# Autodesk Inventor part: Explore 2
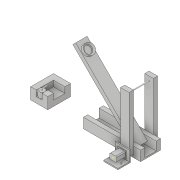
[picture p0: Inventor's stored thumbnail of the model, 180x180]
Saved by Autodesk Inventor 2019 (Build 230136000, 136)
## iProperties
Created: 2020-02
Part Number: Explore 2
Material: Generic
Document SubType Name: Modeling
Designer: Naveen G
Density: 1 g/cm^3
Appearance: Default
Author: Naveen G
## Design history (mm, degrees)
sketch "Sketch1"
  geometry: 1 further point
sketch "Sketch2"
  geometry: L1 (0, 0)-(40, 0); L2 (40, 0)-(40, 15); L3 (40, 15)-(-160, 15); L4 (-160, 15)-(-160, -15); L5 (-160, -15)-(40, -15); L6 (40, -15)-(40, 15)
  constraints: 12 end point, 3 perpendicular, 1 horizontal, 1 point on line
  dimensions: "d0" = 40 distance of L1.start L1.end; "d1" = 15 distance of L1.end L2.end; "d2" = 200 distance of L2.end L3.end; "d3" = 30 distance of L3.end L4.end; "d4" = 200 distance of L4.end L5.end
extrude "Extrusion1" new body sketch "Sketch2" distance "d5" = 15; taper "d6" = 0 deg
sketch "Sketch3"
  geometry: L1 (0, 0)-(0, -10); L2 (0, -10)-(10, 0); L3 (10, 0)-(-202.132, 212.132); L4 (0, -10)-(-212.132, 202.132); L5 (0, -10)-(300, -10); L6 (-212.132, 202.132)-(-202.132, 212.132)
  constraints: 12 end point, 2 perpendicular, 1 equal length, 1 horizontal, 1 vertical
  dimensions: "d7" = 10 distance of L1.start L1.end; "d8" = 45 deg angle of L2 L1; "d9" = 300 distance of L2.end L3.end; "d10" = 90 deg angle of L3 L2 (derived); "d11" = 300 distance of L1.end L4.end; "d12" = 135 deg angle of L5 L4
sketch "Sketch4"
  geometry: 1 further point
extrude "Extrusion2" join sketch "Sketch3" distance "d13" = 40; taper "d14" = 0 deg
sketch "Sketch5"
  geometry: L1 (0, 0)-(40, 0); L2 (40, -15)-(40, 15) reference; L3 (40, 15)-(-160, 15); L4 (40, 15)-(-5, 15) reference; L5 (-160, 15)-(-160, -15) reference; L6 (-160, 15)-(-160, -15); L7 (-160, -15)-(40, -15) reference; L8 (-160, -15)-(40, -15); L9 (40, -15)-(40, 15)
  constraints: 10 end point, 2 collinear, 2 perpendicular, 1 midpoint
  dimensions: "d15" = 200 distance of L2.end L3.end
extrude "Extrusion3" join sketch "Sketch5" distance "d16" = 15; taper "d17" = 0 deg
sketch "Sketch6"
  geometry: L1 (0, 0)-(0, -15); L2 (-160, -15)-(40, -15) reference; L3 (0, -15)-(15, -15); L4 (15, -15)-(15, 185); L5 (15, 185)-(15, -2.705); L6 (15, 185)-(-15, 185); L7 (-15, 185)-(-15, -15); L8 (-15, -15)-(0, -15)
  constraints: 14 end point, 4 perpendicular, 3 point on line, 1 vertical
  dimensions: "d18" = 15 distance of L1.end L3.end; "d19" = 200 distance of L3.end L4.end; "d20" = 30 distance of L4.end L6.end; "d21" = 200 distance of L6.end L7.end
extrude "Extrusion4" join sketch "Sketch6" distance "d22" = 15; taper "d23" = 0 deg
sketch "Sketch7"
  geometry: L1 (0, 0)-(0, 15) reference; L2 (0, 0)-(0, 70); L3 (0, 70)-(200, 70); L4 (200, 70)-(200, 0); L5 (200, 0)-(0, 0) reference; L6 (200, 0)-(0, 0); 1 further point
  constraints: 8 end point, 2 collinear, 2 perpendicular
  dimensions: "d24" = 70 distance of L1.start L2.end; "d25" = 200 distance of L2.end L3.end; "d26" = 200 distance of L4.end L1.start (derived)
extrude "Extrusion5" join sketch "Sketch7" distance "d27" = 5; taper "d28" = 0 deg
fillet "Fillet1" dims "d29" = 5
fillet "Fillet2" dims "d30" = 5
sketch "Sketch8"
  geometry: 1 further point
sketch "Sketch9"
  geometry: L1 (-15, -10)-(-15, 185) reference; L2 (-15, 185)-(15, 185) reference; L3 (-15, 185)-(15, 185); L4 (15, 185)-(15, -15); L5 (-15, 185)-(-15, -15); L6 (10, -15)-(-10, -15) reference; L7 (-15, -15)-(15, -15); 1 further point
  constraints: 8 end point, 1 collinear, 1 perpendicular, 1 point on line
  dimensions: "d31" = 30 distance of L1.end L2.end (derived); "d32" = 200 distance of L2.end L4.end; "d33" = 200 distance of L1.end L5.end; "d34" = 30 distance of L5.end L4.end (derived)
extrude "Extrusion6" join sketch "Sketch9" distance "d35" = 15; taper "d36" = 0 deg
fillet "Fillet3" dims "d37" = 5
sketch "Sketch10"
  geometry: L1 (-15, 185)-(15, 185) reference; L2 (0, 185)-(0, 170); C1 r 2 at (0, 170); 1 further point
  constraints: 2 end point, 1 centre point, 1 coincident, 1 midpoint, 1 vertical
  dimensions: "d38" = 15 distance of L2.start L2.end; "d39" = 4 diameter of C1
extrude "Extrusion7" join sketch "Sketch10" distance "d40" = 70; taper "d41" = 0 deg
sketch "Sketch11"
  geometry: L1 (0, 0)-(0, 40) reference; L2 (0, 0)-(0, 20); L3 (0, 20)-(-30, 20); C1 r 17.5 at (-30, 20); C2 r 12.5 at (-30, 20); 1 further point
  constraints: 4 end point, 2 centre point, 2 coincident, 1 midpoint, 1 perpendicular
  dimensions: "d42" = 20 distance of L1.start L2.end (derived); "d43" = 30 distance of L2.end L3.end; "d44" = 35 diameter of C1; "d45" = 25 diameter of C2
extrude "Extrusion8" join sketch "Sketch11" distance "d46" = 10; taper "d47" = 0 deg
chamfer "Chamfer1" distance "d48" = 5; stored, may be unused: second distance "d49" = 1.25, angle "d50" = 45 deg
sketch "Sketch12"
  geometry: C1 r 3.5 at (0, 0); 1 further point
  constraints: 1 centre point, 1 coincident
  dimensions: "d51" = 7 diameter of C1
extrude "Extrusion9" join sketch "Sketch12" distance "d52" = 5; taper "d53" = 0 deg
sketch "Sketch13"
  geometry: C1 r 3.5 at (0, 0); 1 further point
  constraints: 1 centre point, 1 coincident
extrude "Extrusion10" join sketch "Sketch13" distance "d54" = 5; taper "d55" = 0 deg
fillet "Fillet4" dims "d56" = 3
sketch "Sketch14"
  geometry: L1 (0, 0)-(25, 0); L2 (25, 0)-(25, 20); L3 (25, 20)-(-25, 20); L4 (-25, 20)-(-25, -20); L5 (-160, -20)-(40, -20) reference; L6 (25, -20)-(25, 0); C1 r 0.5 at (0, 0) reference; 1 further point
  constraints: 10 end point, 4 perpendicular, 3 point on line, 1 horizontal
  dimensions: "d57" = 25 distance of L1.start L1.end; "d58" = 20 distance of L1.end L2.end; "d59" = 50 distance of L2.end L3.end
extrude "Extrusion11" join sketch "Sketch14" distance "d60" = 4; taper "d61" = 0 deg
sketch "Sketch15"
  geometry: L1 (-25, 20)-(-25, -20) reference; L2 (-25, -20)-(25, -20); L3 (25, -20)-(25, -16); L4 (25, -16)-(-25, -16); L5 (-25, -16)-(-25, -20); 1 further point
  constraints: 8 end point, 2 parallel, 1 horizontal, 1 perpendicular
  dimensions: "d62" = 50 distance of L4.end L3.end; "d63" = 4 distance of L3.end L2.end
extrude "Extrusion12" join sketch "Sketch15" distance "d64" = 40; taper "d65" = 0 deg
sketch "Sketch16"
  geometry: L1 (0, -40)-(50, -40) reference; L2 (0, -40)-(0, -20); L3 (0, 4)-(0, -40) reference; L4 (0, -20)-(50, -20); L5 (50, -20)-(42, -20); L6 (42, -20)-(0, -20); L7 (0, -20)-(7.932, -20); L8 (0, -20)-(8, -20); C1 r 2 at (42, -20); C2 r 2 at (8, -20); 1 further point
  constraints: 12 end point, 4 point on line, 2 centre point, 2 coincident, 2 perpendicular
  dimensions: "d66" = 20 distance of L1.start L2.end; "d67" = 50 distance of L2.end L4.end; "d68" = 8 distance of L4.end L5.end; "d69" = 8 distance of L2.end L8.end; "d70" = 4 diameter of C1; "d71" = 4 diameter of C2
extrude "Extrusion13" join sketch "Sketch16" distance "d72" = 3; taper "d73" = 0 deg
sketch "Sketch17"
  geometry: L1 (0, 0)-(0, -12.5); L2 (0, -12.5)-(15, -12.5); L3 (15, -12.5)-(15, 12.5); L4 (15, 185)-(15, -10) reference; L5 (15, 12.5)-(-15, 12.5); L6 (-15, 12.5)-(-15, -12.5); L7 (-15, -12.5)-(0, -12.5); C1 r 0.5 at (0, 0) reference; 1 further point
  constraints: 12 end point, 2 point on line, 1 horizontal, 1 perpendicular, 1 vertical
  dimensions: "d74" = 12.5 distance of L1.start L1.end; "d75" = 15 distance of L1.end L2.end; "d76" = 25 distance of L2.end L3.end; "d77" = 30 distance of L3.end L5.end; "d78" = 25 distance of L5.end L6.end
sketch "Sketch18"
  geometry: L1 (15, 185)-(15, -10) reference; L2 (15, 12.495)-(15, 6.245); L3 (15, 0)-(15, -6.25); L4 (15, -6.25)-(15, -12.5); L5 (15, -12.5)-(15, 12.495); 1 further point
  constraints: 8 end point, 5 point on line, 1 collinear
  dimensions: "d79" = 6.25 distance of L2.start L2.end; "d80" = 6.25 distance of L3.start L3.end; "d81" = 6.25 distance of L3.end L4.end
sketch "Sketch19"
  geometry: 1 further point
sketch "Sketch20"
  geometry: L1 (-15, -10)-(-15, 185) reference; L2 (-15, 11.25)-(-15, 9.383); L3 (-15, 5)-(-15, -7.5); L4 (-25, 15)-(0, -10) reference; C1 r 3.25 at (16.5, 6.253); C2 r 3.25 at (16.5, -6.247); C3 r 3.25 at (-16.5, -6.247); A1 r 3.25 centre (-16.5, 6.5) between (-15, 9.383) and (-14.202, 4.202); 1 further point
  constraints: 5 point on line, 4 centre point, 4 end point, 2 point on circle
  dimensions: "d82" = 6.25 distance of L2.start L3.start; "d83" = 12.5 distance of L3.start L3.end; "d84" = 6.5 diameter of C1; "d85" = 6.5 diameter of C2; "d86" = 6.5 diameter of A1; "d87" = 6.5 diameter of C3
extrude "Extrusion14" join sketch "Sketch17" distance "d88" = 2; taper "d89" = 0 deg
sketch "Sketch21"
  geometry: L1 (0, 0)-(12, 0); L2 (12, 0)-(12, 9.5); L3 (12, 9.5)-(-12, 9.5); L4 (-12, 9.5)-(-12, -9.5); L5 (-12, -9.5)-(12, -9.5); L6 (12, 0)-(12, -9.5); C1 r 3.5 at (0, 0) reference; 1 further point
  constraints: 12 end point, 2 perpendicular, 2 vertical, 1 horizontal, 1 point on line
  dimensions: "d90" = 12 distance of L1.start L1.end; "d91" = 9.5 distance of L1.end L2.end; "d92" = 24 distance of L2.end L3.end; "d93" = 19 distance of L3.end L4.end; "d94" = 24 distance of L4.end L5.end; "d95" = 9.5 distance of L1.end L5.end (derived)
extrude "Extrusion15" join sketch "Sketch21" distance "d96" = 30; taper "d97" = 0 deg
sketch "Sketch22"
  geometry: C1 r 0.5 at (0, 0) reference; C2 r 3.5 at (0, 0); 1 further point
  constraints: 1 centre point, 1 coincident
  dimensions: "d98" = 7 diameter of C2
sketch "Sketch23"
  geometry: 1 further point
sketch "Sketch24"
  geometry: C1 r 3.5 at (0, 0); 1 further point
  constraints: 1 centre point, 1 coincident
  dimensions: "d99" = 7 diameter of C1
extrude "Extrusion16" join sketch "Sketch24" distance "d100" = 30; taper "d101" = 0 deg
fillet "Fillet5" dims "d102" = 3
sketch "Sketch25"
  geometry: L1 (0, 70)-(0, 0) reference; L2 (0, 0)-(-120, 0); L3 (-120, 0)-(-120, 10); L4 (-120, 10)-(-120, 15); L5 (-52.132, 15)-(135, 15) reference; L6 (-120, 15)-(-120, 75); L7 (-120, 75)-(-180, 75); L8 (-180, 75)-(-180, -5); L9 (-180, -5)-(-120, -5); L10 (-120, -5)-(-120, 75); 1 further point
  constraints: 16 end point, 2 horizontal, 2 parallel, 2 perpendicular, 2 vertical, 1 point on line
  dimensions: "d103" = 120 distance of L1.end L2.end; "d104" = 10 distance of L2.end L3.end; "d105" = 60 distance of L4.end L6.end; "d106" = 60 distance of L9.end L8.end; "d107" = 80 distance of L8.end L7.end
extrude "Extrusion17" join sketch "Sketch25" distance "d108" = 20; taper "d109" = 0 deg
sketch "Sketch26"
  geometry: L1 (-120, 5)-(-180, 5) reference; L2 (-120, 5)-(-180, 5); L3 (-180, 5)-(-180, -15); L4 (-180, -15)-(-120, -15); L5 (-120, -15)-(-120, 5); 1 further point
  constraints: 8 end point, 2 parallel, 1 horizontal, 1 perpendicular
  dimensions: "d110" = 60 distance of L4.end L3.end; "d111" = 20 distance of L3.end L2.end
extrude "Extrusion18" join sketch "Sketch26" distance "d112" = 20; taper "d113" = 0 deg
sketch "Sketch27"
  geometry: L1 (-180, -75)-(-120, -75) reference; L2 (-180, -75)-(-160, -75); L3 (-160, -75)-(-160, -15); L4 (-160, -15)-(-180, -15); L5 (-180, -15)-(-180, -75); 1 further point
  constraints: 8 end point, 2 parallel, 1 horizontal, 1 perpendicular
  dimensions: "d114" = 20 distance of L4.end L3.end; "d115" = 60 distance of L3.end L2.end
extrude "Extrusion19" join sketch "Sketch27" distance "d116" = 20; taper "d117" = 0 deg
sketch "Sketch28"
  geometry: L1 (-120, -75)-(-140, -75); L2 (-140, -75)-(-140, -55); L3 (-140, -55)-(-120, -55); L4 (-120, -55)-(-120, -75); 1 further point
  constraints: 8 end point, 2 parallel, 1 horizontal, 1 perpendicular
  dimensions: "d118" = 20 distance of L2.end L3.end; "d119" = 20 distance of L1.end L2.end
extrude "Extrusion20" join sketch "Sketch28" distance "d120" = 20; taper "d121" = 0 deg
sketch "Sketch29"
  geometry: L1 (-160, -75)-(-160, -15) reference; L2 (-160, -75)-(-150, -75); L3 (-160, -75)-(-140, -75) reference; L4 (-150, -75)-(-160, -75); L5 (-160, -75)-(-150, -75); L6 (-150, -75)-(-150, -65); C1 r 10 at (-150, -65); 1 further point
  constraints: 8 end point, 2 collinear, 1 centre point, 1 coincident, 1 midpoint, 1 vertical
  dimensions: "d122" = 10 distance of L1.start L2.end (derived); "d123" = 10 distance of L2.end L1.start (derived); "d124" = 10 distance of L2.end L6.end; "d125" = 20 diameter of C1
extrude "Extrusion21" join sketch "Sketch29" distance "d126" = 20; taper "d127" = 0 deg
sketch "Sketch30"
  geometry: L1 (-120, -75)-(-180, -75) reference; L2 (-150, -75)-(-150, -65); C1 r 1.15 at (-150, -65); 1 further point
  constraints: 2 end point, 1 centre point, 1 coincident, 1 midpoint, 1 vertical
  dimensions: "d128" = 10 distance of L2.start L2.end; "d129" = 2.3 diameter of C1
extrude "Extrusion22" join sketch "Sketch30" distance "d130" = 3; taper "d131" = 0 deg
sketch "Sketch31"
  geometry: L1 (0, 0)-(0.483, 0); L2 (0.483, 0)-(0.483, 0.339); L3 (0.483, 0.339)-(0, 0.339); L4 (0, 0.339)-(0, 0); 1 further point
  constraints: 8 end point, 2 parallel, 1 horizontal, 1 perpendicular
extrude "Extrusion23" join sketch "Sketch31" distance "d132" = 0.3; taper "d133" = 0 deg
sketch "Sketch32"
  geometry: L1 (1.15, 0)-(-1.15, 0) reference; L2 (0, 0)-(0, 2.3); L3 (0, 2.3)-(0, 1.15); C1 r 1.152 at (0, 1.15); 1 further point
  constraints: 4 end point, 2 midpoint, 1 centre point, 1 coincident, 1 vertical
  dimensions: "d134" = 2.3 distance of L2.start L2.end; "d135" = 1.15 distance of L2.end L3.end
extrude "Extrusion24" join sketch "Sketch32" stored distance "d136" = 40; taper "d137" = 0 deg
body "Solid1"
